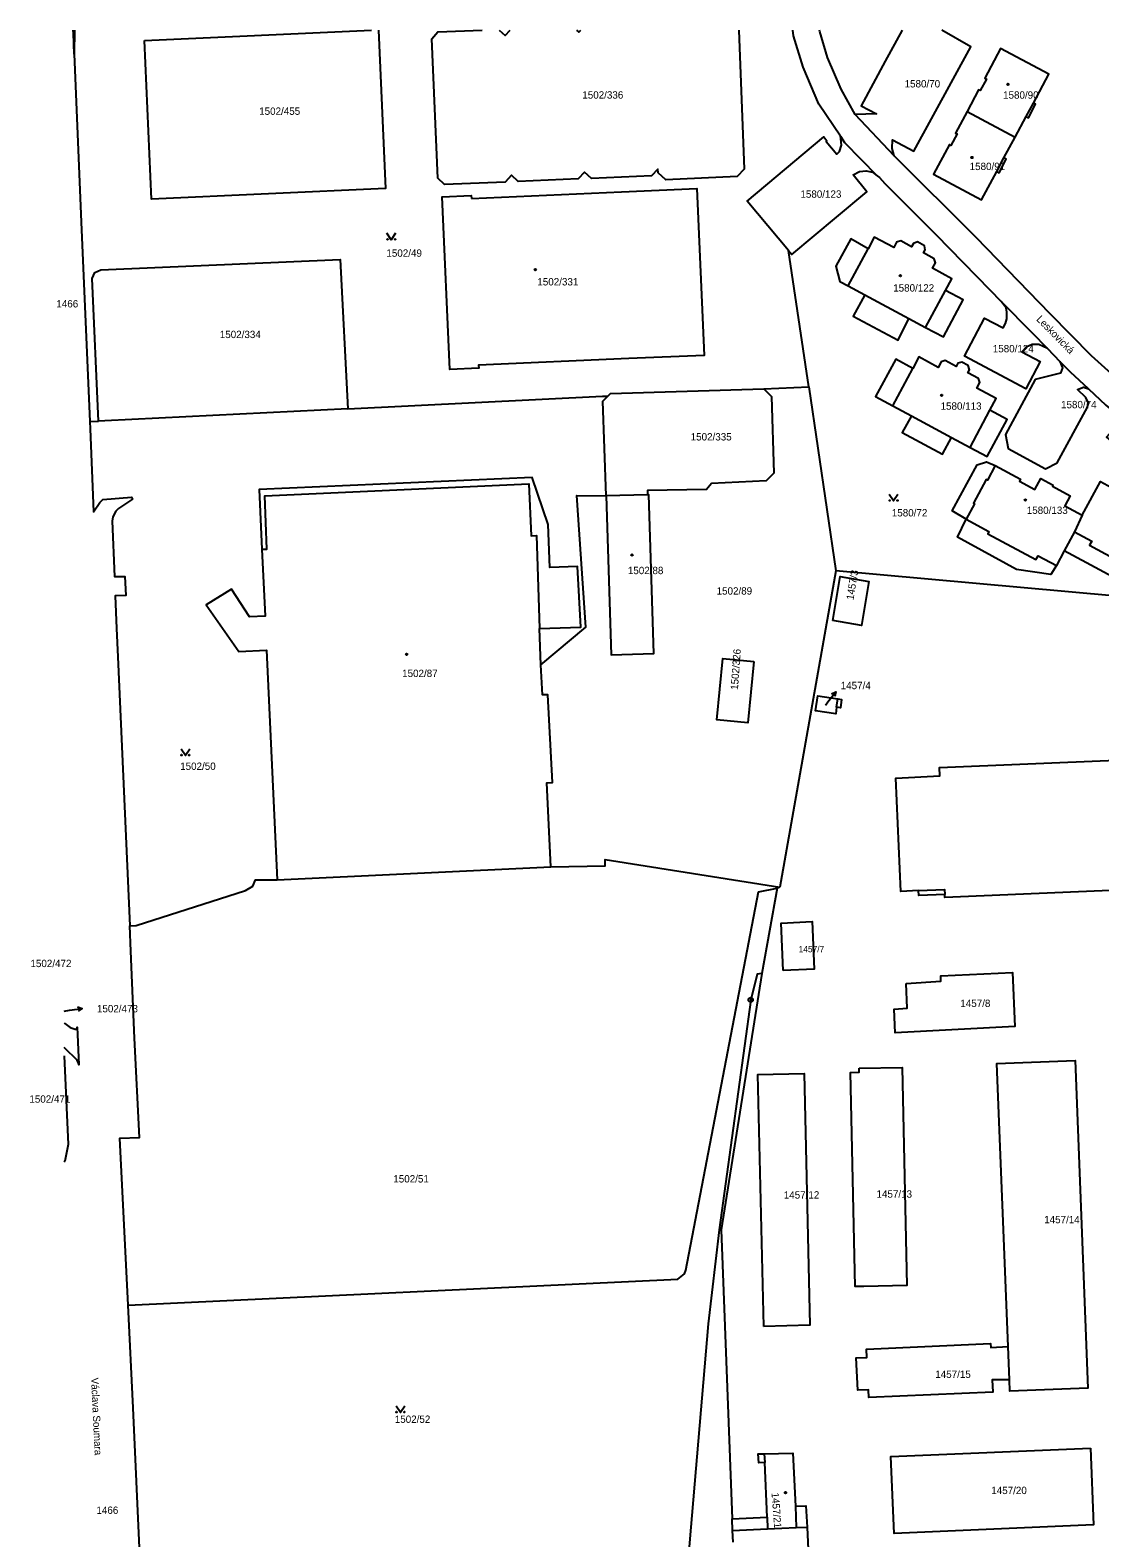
# Model space of a CAD drawing. Extents: x -736397 to -735924, y -1118983 to -1118245.
# Drawn here: x -736396.8 to -736149.3, y -1118593.4 to -1118244.9 of the extents above; entities that cross this region are included whole.
import ezdxf

# ---------------------------------------------------------------- set-up
doc = ezdxf.new("R2010")
doc.units = 0
for name, color, linetype in [('Vrstva 1', 7, 'Continuous'), ('Vrstva 15', 7, 'Continuous'), ('Vrstva 16', 7, 'Continuous'), ('Vrstva 18', 7, 'Continuous'), ('Vrstva 19', 7, 'Continuous'), ('Vrstva 25', 7, 'Continuous'), ('Vrstva 4', 7, 'Continuous')]:
    doc.layers.add(name, color=color, linetype=linetype)

msp = doc.modelspace()

# ---------------------------------------------------------------- linework, layer by layer
at = {"layer": 'Vrstva 1'}
for p, q in [((-736196.9, -1118273.97), (-736205.86, -1118264.4)), ((-736180.01, -1118263.7), (-736168.9, -1118269.62)), ((-736168.9, -1118269.62), (-736166.35, -1118264.86)), ((-736171.47, -1118274.44), (-736168.9, -1118269.62)), ((-736216.6, -1118327.37), (-736221.31, -1118295.84)), ((-736207.53, -1118304.03), (-736203.67, -1118306.1)), ((-736193.48, -1118311.54), (-736189.63, -1118313.6)), ((-736161.4, -1118318.52), (-736158.52, -1118321.48)), ((-736227.02, -1118327.84), (-736216.6, -1118327.37)), ((-736216.6, -1118327.37), (-736210.35, -1118369.86)), ((-736197.2, -1118331.72), (-736192.89, -1118334.04)), ((-736382.97, -1118335.35), (-736380.97, -1118335.25)), ((-736183.59, -1118339.04), (-736179.32, -1118341.34)), ((-736253.92, -1118352.29), (-736263.51, -1118352.52)), ((-736153.37, -1118357.01), (-736155.13, -1118360.86)), ((-736155.13, -1118360.86), (-736157.52, -1118365.27)), ((-736157.52, -1118365.27), (-736159.33, -1118368.64)), ((-736210.35, -1118369.86), (-736223.29, -1118442.99)), ((-736278.61, -1118391.65), (-736278.89, -1118383.2)), ((-736339.59, -1118441.28), (-736276.27, -1118438.27)), ((-736223.96, -1118443.23), (-736227.49, -1118462.99)), ((-736223.29, -1118442.99), (-736223.96, -1118443.23)), ((-736170.23, -1118556.87), (-736170.53, -1118549.22)), ((-736226.28, -1118588.66), (-736226.83, -1118576.02)), ((-736234.35, -1118589.01), (-736226.28, -1118588.66)), ((-736226.28, -1118588.66), (-736226.16, -1118591.34)), ((-736234.25, -1118591.7), (-736234.35, -1118589.01)), ((-736234.13, -1118594.46), (-736234.25, -1118591.7)), ((-736226.16, -1118591.34), (-736219.52, -1118591.05)), ((-736219.52, -1118591.05), (-736217, -1118590.94))]:
    msp.add_line(p, q, dxfattribs=at)
for points in [[(-736386.56, -1118250.47), (-736386.76, -1118245.61), (-736386.79, -1118244.9)], [(-736386.48, -1118244.9), (-736386.56, -1118250.47)], [(-736370.31, -1118247.27), (-736317.79, -1118244.9)], [(-736316.13, -1118244.9), (-736314.51, -1118281.52), (-736368.67, -1118283.94), (-736370.31, -1118247.27)], [(-736232.79, -1118244.9), (-736231.55, -1118277.05), (-736233.16, -1118278.76), (-736249.69, -1118279.52), (-736251.49, -1118277.88), (-736251.56, -1118277), (-736252.98, -1118278.56), (-736266.92, -1118279.18), (-736268.5, -1118277.72), (-736269.94, -1118279.28), (-736283.88, -1118279.92), (-736285.42, -1118278.44), (-736286.86, -1118280.01), (-736300.87, -1118280.61), (-736302.43, -1118279.1), (-736303.83, -1118246.9), (-736302.41, -1118245.32), (-736292.19, -1118244.9)], [(-736288.27, -1118244.9), (-736286.84, -1118246.15), (-736285.67, -1118244.9)], [(-736270.39, -1118244.9), (-736269.84, -1118245.38), (-736269.39, -1118244.9)], [(-736209.32, -1118269.37), (-736214.28, -1118262.01), (-736217.93, -1118253.42), (-736220.19, -1118246.22), (-736220.33, -1118244.9)], [(-736205.86, -1118264.4), (-736209.12, -1118258.56), (-736212.28, -1118251.18), (-736214.09, -1118245.17), (-736214.12, -1118244.9)], [(-736195.03, -1118244.9), (-736198.94, -1118252.09), (-736204.54, -1118262.41), (-736200.99, -1118264.26), (-736205.86, -1118264.4)], [(-736196.9, -1118273.97), (-736197.36, -1118272.28), (-736197.27, -1118270.22), (-736192.36, -1118272.89), (-736179.12, -1118248.78), (-736185.85, -1118244.9)], [(-736386.56, -1118250.47), (-736384.87, -1118291.08), (-736382.97, -1118335.35)], [(-736164.68, -1118261.74), (-736161.13, -1118255.1), (-736172.25, -1118249.17), (-736175.91, -1118256.02), (-736175.55, -1118256.21), (-736176.97, -1118258.86), (-736177.33, -1118258.67), (-736180.01, -1118263.7)], [(-736180.01, -1118263.7), (-736182.67, -1118268.67), (-736182.31, -1118268.86), (-736183.73, -1118271.53), (-736184.09, -1118271.34), (-736187.77, -1118278.22), (-736176.66, -1118284.14), (-736173.14, -1118277.56)], [(-736166.35, -1118264.86), (-736165.83, -1118265.14), (-736164.16, -1118262.02), (-736164.68, -1118261.74)], [(-736221.31, -1118295.84), (-736230.85, -1118284.43), (-736213.13, -1118269.57), (-736212.43, -1118270.47), (-736212.64, -1118270.67), (-736210.17, -1118273.58), (-736209.52, -1118272.91), (-736209.04, -1118271.52), (-736209.23, -1118270.05), (-736209.32, -1118269.37)], [(-736209.32, -1118269.37), (-736208.33, -1118270.84), (-736200.79, -1118278.54)], [(-736143.63, -1118327.06), (-736151.23, -1118320.2), (-736160.8, -1118310.46), (-736177.91, -1118292.84), (-736196.9, -1118273.97)], [(-736173.14, -1118277.56), (-736172.61, -1118277.84), (-736170.96, -1118274.71), (-736171.47, -1118274.44)], [(-736221.31, -1118295.84), (-736220.52, -1118296.79), (-736210.2, -1118288.12), (-736203.19, -1118282.24), (-736206.36, -1118278.37), (-736204.91, -1118277.59), (-736203.38, -1118277.39), (-736201.86, -1118277.7), (-736200.79, -1118278.54)], [(-736200.79, -1118278.54), (-736200.24, -1118278.97), (-736199.05, -1118280.35), (-736187.15, -1118292.22), (-736174.77, -1118304.95), (-736172.1, -1118307.65)], [(-736294.67, -1118283.81), (-736259.92, -1118282.25), (-736242.53, -1118281.51), (-736240.85, -1118320.09), (-736258.25, -1118320.8), (-736293, -1118322.34), (-736292.98, -1118323.01), (-736299.65, -1118323.31), (-736301.44, -1118283.43), (-736294.71, -1118283.08), (-736294.67, -1118283.81)], [(-736202.92, -1118295.43), (-736206.92, -1118293.14), (-736210.39, -1118299.46), (-736209.47, -1118302.98), (-736207.53, -1118304.03)], [(-736185.01, -1118305.05), (-736183.56, -1118302.36), (-736188.04, -1118299.95), (-736187.33, -1118298.7), (-736187.62, -1118297.77), (-736190.11, -1118296.41), (-736189.71, -1118295.69), (-736189.87, -1118294.76), (-736191.46, -1118293.85), (-736192.4, -1118294.21), (-736192.83, -1118294.97), (-736195.3, -1118293.56), (-736196.31, -1118293.93), (-736196.98, -1118295.15), (-736201.47, -1118292.73), (-736202.92, -1118295.43)], [(-736380.97, -1118335.25), (-736382.38, -1118302.33), (-736381.78, -1118300.94), (-736380.42, -1118300.27), (-736325.03, -1118297.95), (-736323.26, -1118332.43)], [(-736203.67, -1118306.1), (-736206.33, -1118310.98), (-736195.98, -1118316.55), (-736193.48, -1118311.54)], [(-736189.63, -1118313.6), (-736185.5, -1118315.82), (-736180.9, -1118307.27), (-736185.01, -1118305.05)], [(-736161.4, -1118318.52), (-736163.41, -1118317.56), (-736164.95, -1118317.56), (-736166.33, -1118318.15), (-736167.36, -1118319.29), (-736163.09, -1118321.53), (-736166.41, -1118327.84), (-736180.58, -1118320.28), (-736175.96, -1118311.46), (-736171.64, -1118313.71), (-736171.13, -1118312.71), (-736170.84, -1118311.64), (-736170.78, -1118310.09), (-736171, -1118309.11), (-736172.1, -1118307.65)], [(-736172.1, -1118307.65), (-736165.02, -1118314.79), (-736161.4, -1118318.52)], [(-736192.59, -1118323.14), (-736196.5, -1118320.98), (-736201.21, -1118329.56), (-736197.2, -1118331.72)], [(-736174.71, -1118332.75), (-736173.26, -1118330.06), (-736177.73, -1118327.66), (-736177.03, -1118326.38), (-736177.35, -1118325.39), (-736179.87, -1118324.1), (-736179.48, -1118323.4), (-736179.78, -1118322.45), (-736181.19, -1118321.68), (-736182.13, -1118321.87), (-736182.56, -1118322.65), (-736185.07, -1118321.29), (-736185.98, -1118321.55), (-736186.68, -1118322.85), (-736191.14, -1118320.45), (-736192.59, -1118323.14)], [(-736158.52, -1118321.48), (-736157.94, -1118322.93), (-736158.41, -1118324.22), (-736164.24, -1118325.69), (-736171.13, -1118338.38), (-736170.54, -1118341.64), (-736161.89, -1118346.28), (-736159.17, -1118344.92), (-736152.17, -1118332.06), (-736151.99, -1118330.98), (-736152.51, -1118329.78), (-736154.47, -1118327.94), (-736153.08, -1118327.41), (-736151.91, -1118327.84)], [(-736151.91, -1118327.84), (-736156.1, -1118323.97), (-736158.52, -1118321.48)], [(-736323.26, -1118332.43), (-736264.33, -1118329.54), (-736263.09, -1118329.48)], [(-736263.51, -1118352.52), (-736264.29, -1118330.68), (-736263.09, -1118329.48)], [(-736263.09, -1118329.48), (-736262.47, -1118328.86), (-736227.02, -1118327.84)], [(-736227.02, -1118327.84), (-736225.29, -1118329.61), (-736224.71, -1118347.31), (-736226.46, -1118349.08), (-736239.12, -1118349.69), (-736240.31, -1118351.05), (-736253.91, -1118351.34), (-736253.92, -1118352.29)], [(-736151.91, -1118327.84), (-736147.88, -1118331.57), (-736145.97, -1118333.22), (-736145.45, -1118334.65), (-736145.53, -1118336), (-736146.42, -1118337.49), (-736147.72, -1118339), (-736142.73, -1118343.24), (-736132.28, -1118350.99), (-736128.12, -1118353.73), (-736123.41, -1118356.52), (-736121.25, -1118353.28), (-736120.22, -1118352.62), (-736118.6, -1118352.53), (-736113.2, -1118355.5)], [(-736323.26, -1118332.43), (-736379.45, -1118335.18), (-736380.97, -1118335.25)], [(-736192.89, -1118334.04), (-736195.02, -1118337.92), (-736185.69, -1118342.95), (-736183.59, -1118339.04)], [(-736179.32, -1118341.34), (-736175.34, -1118343.49), (-736170.74, -1118334.88), (-736174.71, -1118332.75)], [(-736382.97, -1118335.35), (-736382.9, -1118337.04), (-736382.07, -1118356.27), (-736380.61, -1118354.06), (-736379.94, -1118353.36), (-736373.34, -1118352.88), (-736373.1, -1118353.35), (-736376.34, -1118355.5), (-736376.92, -1118356.11), (-736377.6, -1118357.41), (-736377.79, -1118358.37), (-736377.24, -1118371.23), (-736374.82, -1118371.18), (-736374.59, -1118375.59), (-736377.07, -1118375.65), (-736376.77, -1118383.21), (-736376.46, -1118389.73), (-736373.71, -1118451.92)], [(-736180.2, -1118357.95), (-736183.44, -1118355.99), (-736177.69, -1118345.4), (-736175.48, -1118344.7), (-736173.49, -1118345.53)], [(-736278.89, -1118383.2), (-736269.34, -1118382.88), (-736270.12, -1118368.85), (-736276.55, -1118369.1), (-736276.94, -1118359.16), (-736280.62, -1118348.27), (-736343.76, -1118351.09), (-736343.12, -1118364.89)], [(-736173.49, -1118345.53), (-736167.65, -1118348.66), (-736167.9, -1118349.19), (-736164.35, -1118351.11), (-736162.96, -1118348.52), (-736160.12, -1118350.05), (-736160.24, -1118350.34), (-736156.15, -1118352.56), (-736157.39, -1118354.84), (-736153.37, -1118357.01)], [(-736153.37, -1118357.01), (-736149.18, -1118349.24), (-736144.88, -1118351.55), (-736143.64, -1118349.26), (-736139.62, -1118351.44), (-736139.47, -1118351.16), (-736136.61, -1118352.7), (-736137.97, -1118355.27), (-736134.43, -1118357.19), (-736134.13, -1118356.71), (-736128.51, -1118359.75)], [(-736278.61, -1118391.65), (-736268.18, -1118382.94), (-736270.26, -1118352.5), (-736263.51, -1118352.52)], [(-736263.51, -1118352.52), (-736262.31, -1118389.33), (-736252.49, -1118389.01), (-736253.63, -1118352.28), (-736253.92, -1118352.29)], [(-736159.33, -1118368.64), (-736160.62, -1118370.71), (-736168.54, -1118369.59), (-736182.26, -1118362.08), (-736180.2, -1118357.95)], [(-736343.12, -1118364.89), (-736342.41, -1118380.37), (-736346.04, -1118380.54), (-736350.21, -1118374.13), (-736356.05, -1118377.76), (-736348.49, -1118388.51), (-736342.05, -1118388.21), (-736339.59, -1118441.28)], [(-736135.22, -1118372.18), (-736136.24, -1118373.94), (-736142.22, -1118373.5), (-736157.52, -1118365.27)], [(-736211.1, -1118381.39), (-736209.36, -1118371.23), (-736202.72, -1118372.35), (-736204.47, -1118382.53), (-736211.1, -1118381.39)], [(-736052.29, -1118402.89), (-736052.32, -1118400.48), (-736090.36, -1118393.09), (-736118.86, -1118378.12), (-736124.09, -1118377.65), (-736210.35, -1118369.86)], [(-736276.27, -1118438.27), (-736277.24, -1118418.92), (-736275.94, -1118418.85), (-736276.96, -1118398.51), (-736278.26, -1118398.58), (-736278.61, -1118391.65)], [(-736229.36, -1118390.85), (-736230.76, -1118404.99), (-736237.93, -1118404.33), (-736236.53, -1118390.14), (-736229.36, -1118390.85)], [(-736210.18, -1118401.41), (-736210.39, -1118402.94), (-736215.07, -1118402.21), (-736214.52, -1118398.76), (-736209.91, -1118399.5)], [(-736209.91, -1118399.5), (-736209.05, -1118399.64), (-736209.3, -1118401.55), (-736210.18, -1118401.41)], [(-736191.24, -1118443.78), (-736195.37, -1118444.04), (-736196.5, -1118417.85), (-736186.33, -1118417.24), (-736186.41, -1118415.38), (-736102.77, -1118411.87), (-736101.51, -1118441.88), (-736185.15, -1118445.39), (-736185.18, -1118444.69)], [(-736276.27, -1118438.27), (-736263.74, -1118438.05), (-736263.74, -1118436.64), (-736223.29, -1118442.99)], [(-736373.71, -1118451.92), (-736372.19, -1118451.87), (-736346.97, -1118443.8), (-736345.27, -1118442.76), (-736344.61, -1118441.35), (-736339.59, -1118441.28)], [(-736374.05, -1118539.63), (-736246.89, -1118533.59), (-736245.39, -1118532.38), (-736245.05, -1118531.56), (-736228.27, -1118444.06), (-736223.96, -1118443.23)], [(-736185.18, -1118444.69), (-736191.19, -1118444.94), (-736191.24, -1118443.78)], [(-736374.05, -1118539.63), (-736376, -1118501.01), (-736371.49, -1118500.88), (-736372.62, -1118477.91), (-736373.45, -1118457.79), (-736373.71, -1118451.92)], [(-736222.55, -1118462.28), (-736223, -1118451.3), (-736215.86, -1118450.97), (-736215.36, -1118461.99), (-736222.55, -1118462.28)], [(-736227.49, -1118462.99), (-736228.6, -1118463.11), (-736230.07, -1118469.05), (-736237.36, -1118522.21), (-736239.9, -1118543.95), (-736244.25, -1118594.56), (-736247.64, -1118635.96), (-736251.91, -1118694.01)], [(-736227.49, -1118462.99), (-736236.91, -1118522.19), (-736234.35, -1118589.01)], [(-736194.09, -1118465.26), (-736186.05, -1118464.76), (-736186.08, -1118463.47), (-736169.53, -1118462.71), (-736168.94, -1118475.23), (-736196.63, -1118476.66), (-736196.91, -1118471.19), (-736193.84, -1118470.99), (-736194.09, -1118465.26)], [(-736388.91, -1118474.36), (-736388.76, -1118474.49), (-736387.49, -1118475.48), (-736386.37, -1118475.87), (-736386.18, -1118475.82), (-736386.02, -1118475.71), (-736385.91, -1118475.55), (-736385.86, -1118475.36), (-736385.49, -1118484.1), (-736385.56, -1118483.71), (-736385.7, -1118483.35), (-736385.91, -1118483.01), (-736386.18, -1118482.73), (-736388.45, -1118480.5), (-736388.91, -1118480.08)], [(-736388.91, -1118482), (-736387.98, -1118502.47), (-736388.74, -1118506.37), (-736388.91, -1118506.56)], [(-736170.53, -1118549.22), (-736173.14, -1118483.78), (-736155.03, -1118483.06), (-736152.04, -1118558.85), (-736170.12, -1118559.55), (-736170.23, -1118556.87)], [(-736227, -1118544.55), (-736228.42, -1118486.34), (-736217.72, -1118486.08), (-736216.39, -1118544.28), (-736227, -1118544.55)], [(-736204.96, -1118484.88), (-736195.06, -1118484.71), (-736193.95, -1118535.08), (-736203.87, -1118535.3), (-736205.9, -1118535.32), (-736206.98, -1118485.85), (-736204.94, -1118485.81), (-736204.96, -1118484.88)], [(-736367.65, -1118679.7), (-736368.4, -1118667.4), (-736370.7, -1118612.79), (-736372.92, -1118563.37), (-736374.05, -1118539.63)], [(-736170.23, -1118556.87), (-736174.2, -1118556.92), (-736174.07, -1118559.74), (-736202.71, -1118561.02), (-736202.81, -1118559.18), (-736205.31, -1118559.3), (-736205.63, -1118551.8), (-736203.21, -1118551.72), (-736203.31, -1118549.8), (-736174.59, -1118548.47), (-736174.55, -1118549.43), (-736170.53, -1118549.22)], [(-736226.83, -1118576.02), (-736228.22, -1118576.08), (-736228.32, -1118574.03), (-736226.92, -1118574.04)], [(-736226.92, -1118574.04), (-736220.34, -1118573.85), (-736219.73, -1118586.12)], [(-736151.49, -1118572.69), (-736150.77, -1118590.43), (-736196.91, -1118592.39), (-736197.63, -1118574.65), (-736151.49, -1118572.69)], [(-736219.73, -1118586.12), (-736217.28, -1118586.04), (-736217, -1118590.94)], [(-736217, -1118590.94), (-736214.63, -1118643.77), (-736231.89, -1118644.57)]]:
    msp.add_lwpolyline(points, dxfattribs=at)
at = {"layer": 'Vrstva 16'}
for points in [[(-736212.74, -1118400.9), (-736212.2, -1118400.2), (-736210.36, -1118397.83)], [(-736211.37, -1118398.31), (-736210.36, -1118397.83), (-736210.58, -1118398.93)], [(-736388.91, -1118471.65), (-736387.68, -1118471.46), (-736384.71, -1118471.02)], [(-736385.78, -1118470.67), (-736384.71, -1118471.02), (-736385.63, -1118471.66)]]:
    msp.add_lwpolyline(points, dxfattribs=at)
at = {"layer": 'Vrstva 25'}
for points in [[(-736312.21, -1118291.85), (-736313.21, -1118293.35), (-736314.21, -1118291.85)], [(-736196.02, -1118352.21), (-736197.02, -1118353.71), (-736198.02, -1118352.21)], [(-736359.84, -1118411.07), (-736360.84, -1118412.57), (-736361.84, -1118411.07)], [(-736310.09, -1118562.95), (-736311.09, -1118564.45), (-736312.09, -1118562.95)]]:
    msp.add_lwpolyline(points, dxfattribs=at)
for centre in [(-736314.11, -1118293.25), (-736312.31, -1118293.25), (-736197.92, -1118353.61), (-736196.12, -1118353.61), (-736361.74, -1118412.47), (-736359.94, -1118412.47), (-736311.99, -1118564.35), (-736310.19, -1118564.35)]:
    msp.add_circle(centre, 0.1, dxfattribs=at)
for centre, major_axis in [((-736170.55, -1118257.41), (0.18, 0)), ((-736178.89, -1118274.34), (0.18, 0)), ((-736279.9, -1118300.28), (0.18, 0)), ((-736195.44, -1118301.63), (0.18, 0)), ((-736185.88, -1118329.32), (0.18, 0)), ((-736166.51, -1118353.51), (0.18, 0)), ((-736257.5, -1118366.21), (0.18, 0)), ((-736309.67, -1118389.19), (0.18, 0)), ((-736230.07, -1118469.05), (0.516, 0)), ((-736230.07, -1118469.05), (0.0375, 0)), ((-736222.01, -1118582.99), (0.18, 0))]:
    msp.add_ellipse(centre, major_axis=major_axis, ratio=0.984808, dxfattribs=at)
at = {"layer": 'Vrstva 4'}
for p, q in [((-736166.35, -1118264.86), (-736164.68, -1118261.74)), ((-736173.14, -1118277.56), (-736171.47, -1118274.44)), ((-736207.53, -1118304.03), (-736202.92, -1118295.43)), ((-736203.67, -1118306.1), (-736193.48, -1118311.54)), ((-736189.63, -1118313.6), (-736185.01, -1118305.05)), ((-736197.2, -1118331.72), (-736192.59, -1118323.14)), ((-736192.89, -1118334.04), (-736183.59, -1118339.04)), ((-736179.32, -1118341.34), (-736174.71, -1118332.75)), ((-736210.18, -1118401.41), (-736209.91, -1118399.5)), ((-736226.92, -1118574.04), (-736226.83, -1118576.02)), ((-736219.73, -1118586.12), (-736219.52, -1118591.05)), ((-736234.25, -1118591.7), (-736226.16, -1118591.34))]:
    msp.add_line(p, q, dxfattribs=at)
for points in [[(-736173.49, -1118345.53), (-736175.31, -1118348.91), (-736175.59, -1118348.78), (-736178.54, -1118354.25), (-736178.27, -1118354.41), (-736180.2, -1118357.95)], [(-736343.12, -1118364.89), (-736341.99, -1118364.84), (-736342.44, -1118352.53), (-736281.39, -1118349.79), (-736280.85, -1118361.78), (-736279.6, -1118361.72), (-736278.89, -1118383.2)], [(-736180.2, -1118357.95), (-736174.95, -1118360.81), (-736175.19, -1118361.33), (-736164.07, -1118367.3), (-736163.58, -1118366.38), (-736159.33, -1118368.64)], [(-736155.13, -1118360.86), (-736151.16, -1118363), (-736151.69, -1118363.96), (-736140.59, -1118369.97), (-736140.27, -1118369.43), (-736135.22, -1118372.18)], [(-736191.24, -1118443.78), (-736185.23, -1118443.53), (-736185.18, -1118444.69)]]:
    msp.add_lwpolyline(points, dxfattribs=at)

# ---------------------------------------------------------------- texts
at = {"layer": 'Vrstva 15'}
for s, rotation, p in [('Leskovická', 314.5501, (-736164.11, -1118311.86)), ('Václava Soumara', 272.7407, (-736382.67, -1118556.44))]:
    msp.add_text(s, height=1.7, rotation=rotation, dxfattribs=at).set_placement(p)
at = {"layer": 'Vrstva 16'}
for s, p in [('1466', (-736390.69, -1118309)), ('1457/4', (-736209.24, -1118397.24)), ('1502/472', (-736396.68, -1118461.49)), ('1502/473', (-736381.3, -1118471.94))]:
    msp.add_text(s, height=1.7, dxfattribs=at).set_placement(p)
at = {"layer": 'Vrstva 18'}
for s, height, p in [('1580/70', 1.7, (-736194.46, -1118258.14)), ('1502/336', 1.7, (-736269.02, -1118260.72)), ('1502/455', 1.7, (-736343.77, -1118264.47)), ('1580/123', 1.7, (-736218.56, -1118283.64)), ('1502/49', 1.7, (-736314.34, -1118297.28)), ('1502/334', 1.7, (-736352.88, -1118316.08)), ('1580/124', 1.7, (-736174.06, -1118319.37)), ('1580/74', 1.7, (-736158.27, -1118332.3)), ('1502/335', 1.7, (-736243.95, -1118339.75)), ('1580/72', 1.7, (-736197.42, -1118357.31)), ('1502/89', 1.7, (-736237.95, -1118375.38)), ('1457/4', 0.1, (-736212.74, -1118400.9)), ('1502/50', 1.7, (-736362.05, -1118415.9)), ('1457/7', 1.45, (-736218.98, -1118458.06)), ('1457/8', 1.7, (-736181.57, -1118470.71)), ('1502/471', 1.7, (-736396.93, -1118492.84)), ('1502/51', 1.7, (-736312.74, -1118511.28)), ('1457/12', 1.7, (-736222.41, -1118515)), ('1457/13', 1.7, (-736200.96, -1118514.79)), ('1457/14', 1.7, (-736162.17, -1118520.7)), ('1457/15', 1.7, (-736187.37, -1118556.46)), ('1502/52', 1.7, (-736312.4, -1118566.85)), ('1457/20', 1.7, (-736174.41, -1118583.31)), ('1466', 1.7, (-736381.42, -1118587.88))]:
    msp.add_text(s, height=height, dxfattribs=at).set_placement(p)
for s, rotation, p in [('1457/3', 80.7105, (-736206.29, -1118376.71)), ('1502/326', 85.9093, (-736233.02, -1118397.45))]:
    msp.add_text(s, height=1.7, rotation=rotation, dxfattribs=at).set_placement(p)
at = {"layer": 'Vrstva 19'}
for s, p in [('1580/90', (-736171.68, -1118260.74)), ('1580/91', (-736179.41, -1118277.24)), ('1502/331', (-736279.42, -1118303.91)), ('1580/122', (-736197.1, -1118305.33)), ('1580/113', (-736186.14, -1118332.64)), ('1580/133', (-736166.2, -1118356.73)), ('1502/88', (-736258.48, -1118370.65)), ('1502/87', (-736310.7, -1118394.43))]:
    msp.add_text(s, height=1.7, dxfattribs=at).set_placement(p)
msp.add_text('1457/21', height=1.7, rotation=274.3916, dxfattribs=at).set_placement((-736225.25, -1118583.03))

doc.saveas('drawing.dxf')
